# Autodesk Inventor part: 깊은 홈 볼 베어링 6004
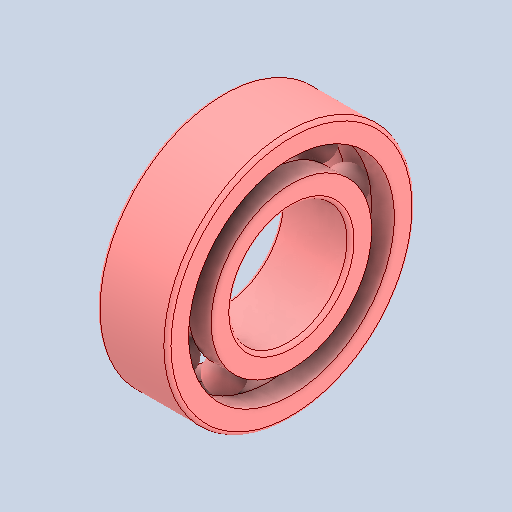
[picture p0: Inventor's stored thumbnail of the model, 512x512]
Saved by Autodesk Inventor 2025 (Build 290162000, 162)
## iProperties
Created: 2026-03
Part Number: 깊은 홈 볼 베어링 6004
Material: 강철, 연강
Description: 깊은 그루브 볼 베어링
Document SubType Name: Modeling
Designer: KDI
Density: 7.85 g/cm^3
Appearance: 기본값
Author: jhkim
Sending System: Autodesk Inventor 2026
Preprocessor: ST-DEVELOPER v20.1
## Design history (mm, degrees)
feature "Solid1"
feature "Solid1:1"
feature "Solid1:2"
feature "Solid1:3"
feature "Solid1:4"
feature "Solid1:5"
feature "Solid1:6"
feature "Solid1:7"
feature "Solid1:8"
feature "Solid1:9"
feature "Solid1:10"
node "솔리드1"
node "솔리드2"
node "솔리드3"
node "솔리드4"
node "솔리드5"
node "솔리드6"
node "솔리드7"
node "솔리드8"
node "솔리드9"
node "솔리드10"
node "솔리드11"
